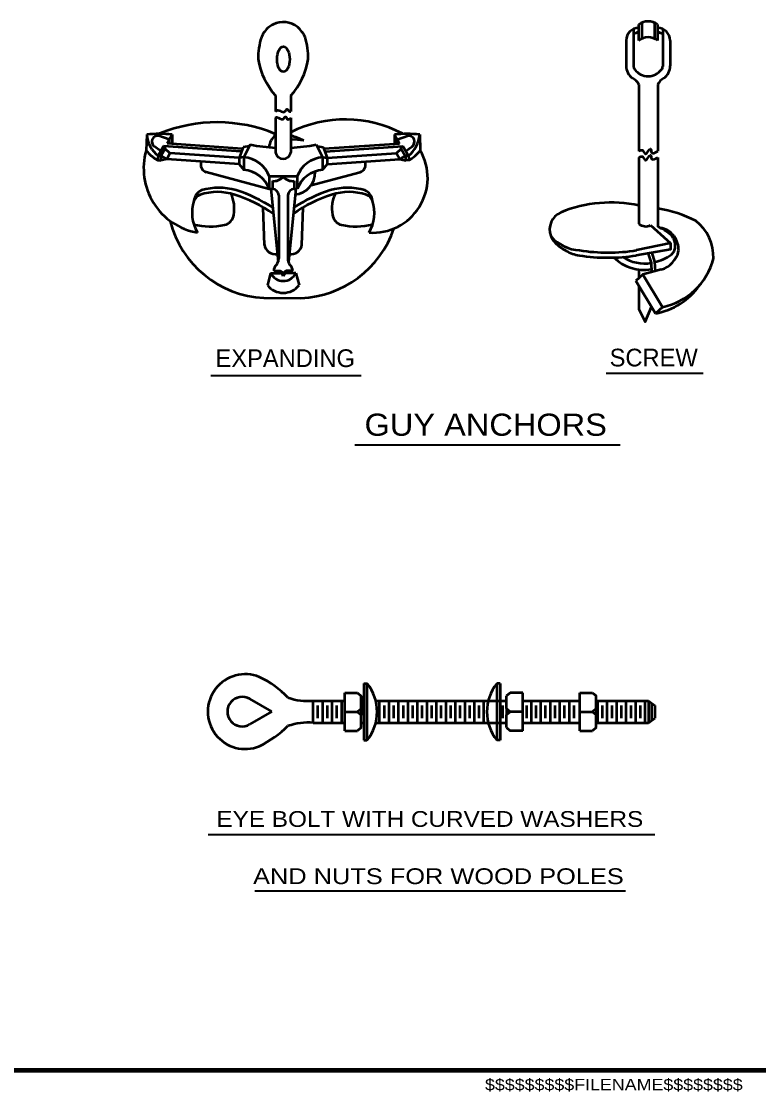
# Model space of a CAD drawing. Extents: x 14808 to 15663, y 10944 to 11488.
# Drawn here: x 15295.9 to 15435.8, y 10951.6 to 11154.7 of the extents above; entities that cross this region are included whole.
import ezdxf
from ezdxf.enums import TextEntityAlignment as Align

# ---------------------------------------------------------------- set-up
doc = ezdxf.new("R2010")
doc.units = 0
doc.header["$LTSCALE"] = 1.2
doc.layers.add('1', color=7, linetype='Continuous', lineweight=53)

msp = doc.modelspace()

# ---------------------------------------------------------------- linework, layer by layer
at = {"layer": '1'}
for p, q in [((15413.033, 11154.123), (15413.033, 11151.123)), ((15413.633, 11154.482), (15413.633, 11151.482)), ((15416.033, 11154.483), (15416.033, 11151.483)), ((15416.633, 11154.123), (15416.633, 11151.123)), ((15412.073, 11153.287), (15412.073, 11146.212)), ((15417.593, 11153.287), (15417.593, 11146.194)), ((15410.633, 11151.123), (15410.633, 11146.323)), ((15419.033, 11151.123), (15419.033, 11146.323)), ((15413.077, 11142.737), (15413.077, 11130.137)), ((15416.677, 11142.737), (15416.677, 11130.137)), ((15344.128, 11140.65), (15344.128, 11137.65)), ((15347.046, 11140.65), (15347.046, 11137.65)), ((15344.128, 11136.45), (15344.128, 11129.85)), ((15347.046, 11136.45), (15347.046, 11129.85)), ((15319.679, 11133.26), (15319.574, 11130.262)), ((15323.963, 11132.331), (15321.977, 11133.015)), ((15324.479, 11133.26), (15323.538, 11131.567)), ((15324.479, 11133.26), (15324.479, 11131.501)), ((15366.695, 11133.26), (15367.626, 11131.585)), ((15366.695, 11133.26), (15366.695, 11131.52)), ((15367.211, 11132.331), (15369.197, 11133.015)), ((15371.495, 11133.26), (15371.6, 11130.262)), ((15322.357, 11130.132), (15321.128, 11130.993)), ((15322.872, 11131.061), (15321.841, 11129.204)), ((15337.613, 11130.03), (15322.872, 11131.061)), ((15323.206, 11130.579), (15323.206, 11131.038)), ((15337.824, 11130.568), (15323.538, 11131.567)), ((15323.963, 11132.331), (15323.963, 11131.537)), ((15339.178, 11131.05), (15337.989, 11130.883)), ((15339.328, 11131.35), (15338.128, 11128.95)), ((15351.846, 11131.35), (15353.046, 11128.95)), ((15351.996, 11131.05), (15353.185, 11130.883)), ((15353.349, 11130.587), (15367.626, 11131.585)), ((15353.561, 11130.03), (15368.302, 11131.061)), ((15367.211, 11132.331), (15367.211, 11131.556)), ((15367.969, 11130.579), (15367.969, 11131.038)), ((15368.302, 11131.061), (15369.333, 11129.204)), ((15368.817, 11130.132), (15370.046, 11130.993)), ((15321.841, 11129.204), (15322.453, 11129.223)), ((15323.47, 11128.587), (15322.453, 11129.223)), ((15324.069, 11129.746), (15323.206, 11130.579)), ((15324.069, 11129.746), (15323.47, 11128.587)), ((15337.237, 11128.825), (15324.069, 11129.746)), ((15338.128, 11128.95), (15337.237, 11128.825)), ((15338.128, 11128.95), (15338.128, 11126.55)), ((15353.046, 11128.95), (15353.046, 11126.55)), ((15353.046, 11128.95), (15353.938, 11128.825)), ((15353.938, 11128.825), (15367.105, 11129.746)), ((15367.105, 11129.746), (15367.969, 11130.579)), ((15367.105, 11129.746), (15367.704, 11128.587)), ((15367.704, 11128.587), (15368.722, 11129.223)), ((15369.333, 11129.204), (15368.722, 11129.223)), ((15323.47, 11128.587), (15322.301, 11128.318)), ((15337.237, 11127.625), (15323.47, 11128.587)), ((15353.938, 11127.625), (15367.704, 11128.587)), ((15367.704, 11128.587), (15368.873, 11128.318)), ((15413.077, 11128.937), (15413.077, 11116.337)), ((15416.677, 11128.937), (15416.677, 11115.727)), ((15342.928, 11122.906), (15330.968, 11126.11)), ((15342.928, 11125.35), (15348.246, 11125.35)), ((15342.928, 11125.35), (15342.928, 11122.906)), ((15348.246, 11125.35), (15348.246, 11122.95)), ((15350.899, 11123.626), (15360.172, 11126.11)), ((15342.928, 11122.95), (15343.528, 11122.95)), ((15343.228, 11122.95), (15344.613, 11109.083)), ((15343.528, 11124.45), (15343.528, 11122.95)), ((15347.946, 11122.95), (15346.561, 11109.083)), ((15347.646, 11124.45), (15347.646, 11122.95)), ((15347.646, 11122.95), (15348.246, 11122.95)), ((15344.728, 11121.75), (15344.728, 11109.75)), ((15346.446, 11121.75), (15346.446, 11109.75)), ((15342.048, 11112.247), (15341.797, 11119.443)), ((15349.126, 11112.247), (15349.377, 11119.443)), ((15415.301, 11116.074), (15419.091, 11112.661)), ((15419.091, 11112.661), (15412.635, 11111.289)), ((15415.546, 11110.836), (15416.072, 11109.115)), ((15416.072, 11109.115), (15416.166, 11107.317)), ((15343.195, 11106.983), (15342.573, 11104.664)), ((15343.195, 11106.983), (15344.995, 11106.983)), ((15343.787, 11107.368), (15344.987, 11107.368)), ((15347.387, 11107.368), (15346.187, 11107.368)), ((15347.995, 11106.983), (15346.195, 11106.983)), ((15347.995, 11106.983), (15348.616, 11104.664)), ((15413.848, 11106.696), (15412.51, 11105.492)), ((15413.077, 11107.661), (15413.077, 11106.002)), ((15417.325, 11107.628), (15413.848, 11106.696)), ((15413.848, 11106.696), (15417.556, 11100.525)), ((15412.51, 11105.492), (15416.219, 11099.32)), ((15341.916, 11102.247), (15348.949, 11102.235)), ((15417.556, 11100.525), (15416.219, 11099.32)), ((15360.882, 11029.095), (15360.882, 11018.295)), ((15360.882, 11029.095), (15361.482, 11029.095)), ((15361.482, 11029.095), (15361.482, 11018.295)), ((15386.146, 11029.095), (15386.146, 11018.295)), ((15386.746, 11029.095), (15386.146, 11029.095)), ((15386.746, 11029.095), (15386.746, 11018.295)), ((15343.394, 11023.735), (15339.237, 11026.135)), ((15351.282, 11021.595), (15351.282, 11025.795)), ((15351.282, 11025.795), (15357.257, 11025.795)), ((15353.082, 11021.595), (15353.082, 11025.795)), ((15354.882, 11021.595), (15354.882, 11025.795)), ((15356.682, 11021.595), (15356.682, 11025.795)), ((15357.282, 11027.295), (15359.682, 11027.295)), ((15360.391, 11025.795), (15360.852, 11025.795)), ((15360.402, 11024.295), (15360.402, 11026.695)), ((15363.14, 11025.795), (15387.886, 11025.795)), ((15363.882, 11021.595), (15363.882, 11025.795)), ((15365.682, 11021.595), (15365.682, 11025.795)), ((15367.482, 11021.595), (15367.482, 11025.795)), ((15369.282, 11021.595), (15369.282, 11025.795)), ((15371.082, 11021.595), (15371.082, 11025.795)), ((15372.882, 11021.595), (15372.882, 11025.795)), ((15374.682, 11021.595), (15374.682, 11025.795)), ((15376.482, 11021.595), (15376.482, 11025.795)), ((15378.282, 11021.595), (15378.282, 11025.795)), ((15380.082, 11021.595), (15380.082, 11025.795)), ((15381.882, 11021.595), (15381.882, 11025.795)), ((15383.682, 11021.595), (15383.682, 11025.795)), ((15388.679, 11027.317), (15387.959, 11026.717)), ((15387.959, 11024.317), (15387.959, 11026.717)), ((15391.079, 11027.317), (15388.679, 11027.317)), ((15390.998, 11025.795), (15401.826, 11025.795)), ((15392.682, 11021.595), (15392.682, 11025.795)), ((15394.482, 11021.595), (15394.482, 11025.795)), ((15396.282, 11021.595), (15396.282, 11025.795)), ((15398.082, 11021.595), (15398.082, 11025.795)), ((15399.882, 11021.595), (15399.882, 11025.795)), ((15401.879, 11027.317), (15404.279, 11027.317)), ((15404.279, 11027.317), (15404.999, 11026.717)), ((15404.938, 11025.795), (15414.882, 11025.795)), ((15404.999, 11024.317), (15404.999, 11026.717)), ((15405.282, 11021.595), (15405.282, 11025.795)), ((15407.082, 11021.595), (15407.082, 11025.795)), ((15408.882, 11021.595), (15408.882, 11025.795)), ((15410.682, 11021.595), (15410.682, 11025.795)), ((15412.482, 11021.595), (15412.482, 11025.795)), ((15414.282, 11021.595), (15414.282, 11025.795)), ((15414.882, 11025.795), (15414.882, 11021.595)), ((15414.882, 11025.795), (15416.082, 11024.895)), ((15343.394, 11023.735), (15339.237, 11021.335)), ((15352.182, 11022.495), (15352.182, 11024.895)), ((15353.982, 11022.495), (15353.982, 11024.895)), ((15355.782, 11022.495), (15355.782, 11024.895)), ((15357.282, 11023.695), (15359.682, 11023.695)), ((15360.402, 11024.295), (15360.402, 11023.095)), ((15364.782, 11022.495), (15364.782, 11024.895)), ((15366.582, 11022.495), (15366.582, 11024.895)), ((15368.382, 11022.495), (15368.382, 11024.895)), ((15370.182, 11022.495), (15370.182, 11024.895)), ((15371.982, 11022.495), (15371.982, 11024.895)), ((15373.782, 11022.495), (15373.782, 11024.895)), ((15375.582, 11022.495), (15375.582, 11024.895)), ((15377.382, 11022.495), (15377.382, 11024.895)), ((15379.182, 11022.495), (15379.182, 11024.895)), ((15380.982, 11022.495), (15380.982, 11024.895)), ((15382.782, 11022.495), (15382.782, 11024.895)), ((15387.289, 11022.495), (15387.289, 11024.895)), ((15387.959, 11024.317), (15387.959, 11023.117)), ((15391.079, 11023.717), (15388.679, 11023.717)), ((15391.782, 11022.495), (15391.782, 11024.895)), ((15393.582, 11022.495), (15393.582, 11024.895)), ((15395.382, 11022.495), (15395.382, 11024.895)), ((15397.182, 11022.495), (15397.182, 11024.895)), ((15398.982, 11022.495), (15398.982, 11024.895)), ((15400.782, 11022.495), (15400.782, 11024.895)), ((15401.879, 11023.717), (15404.279, 11023.717)), ((15404.999, 11024.317), (15404.999, 11023.117)), ((15406.182, 11022.495), (15406.182, 11024.895)), ((15407.982, 11022.495), (15407.982, 11024.895)), ((15409.782, 11022.495), (15409.782, 11024.895)), ((15411.582, 11022.495), (15411.582, 11024.895)), ((15413.382, 11022.495), (15413.382, 11024.895)), ((15415.482, 11025.345), (15415.482, 11022.045)), ((15416.082, 11024.895), (15416.082, 11022.495)), ((15351.282, 11021.595), (15357.257, 11021.595)), ((15360.391, 11021.595), (15360.869, 11021.595)), ((15360.402, 11020.695), (15360.402, 11023.095)), ((15363.14, 11021.595), (15387.971, 11021.595)), ((15387.959, 11020.717), (15387.959, 11023.117)), ((15404.98, 11021.595), (15414.882, 11021.595)), ((15404.999, 11020.717), (15404.999, 11023.117)), ((15414.882, 11021.595), (15416.082, 11022.495)), ((15357.282, 11020.095), (15359.682, 11020.095)), ((15360.402, 11020.695), (15359.682, 11020.095)), ((15387.959, 11020.717), (15388.679, 11020.117)), ((15391.079, 11020.117), (15388.679, 11020.117)), ((15401.879, 11020.117), (15404.279, 11020.117)), ((15404.999, 11020.717), (15404.279, 11020.117)), ((15360.882, 11018.295), (15361.482, 11018.295)), ((15386.746, 11018.295), (15386.146, 11018.295))]:
    msp.add_line(p, q, dxfattribs=at)
at = {"layer": '1', "lineweight": 13}
msp.add_line((15413.077, 11106.08), (15413.077, 11105.845), dxfattribs=at)
at = {"layer": '1', "lineweight": 35}
for p, q in [((15331.87, 11087.501), (15360.407, 11087.501)), ((15406.847, 11087.97), (15425.297, 11087.97))]:
    msp.add_line(p, q, dxfattribs=at)
at = {"layer": '1', "lineweight": 40}
for p, q in [((15359.166, 11074.353), (15409.532, 11074.353)), ((15331.346, 11000.437), (15416.079, 11000.437)), ((15340.173, 10989.71), (15410.512, 10989.71))]:
    msp.add_line(p, q, dxfattribs=at)
at = {"layer": '1', "lineweight": 158}
msp.add_line((15656.868, 10955.64), (14865.268, 10955.64), dxfattribs=at)
at = {"layer": '1'}
for points in [[(15321.841, 11129.204), (15321.709, 11128.417), (15322.301, 11128.318)], [(15323.206, 11130.579), (15322.453, 11129.223), (15322.301, 11128.318)], [(15337.989, 11130.883), (15337.237, 11128.825), (15337.237, 11127.625), (15338.128, 11126.55)], [(15353.185, 11130.883), (15353.938, 11128.825), (15353.938, 11127.625), (15353.046, 11126.55)], [(15367.969, 11130.579), (15368.722, 11129.223), (15368.873, 11128.318)], [(15369.333, 11129.204), (15369.465, 11128.417), (15368.873, 11128.318)], [(15419.091, 11112.661), (15419.091, 11111.461), (15412.591, 11110.315)], [(15414.857, 11110.626), (15415.384, 11108.904), (15415.478, 11107.107)], [(15413.077, 11104.549), (15413.077, 11100.137), (15414.277, 11097.737), (15415.478, 11100.553)], [(15357.282, 11020.095), (15357.282, 11023.695), (15357.282, 11027.295)], [(15359.682, 11027.295), (15360.402, 11026.695), (15360.402, 11024.295), (15359.682, 11023.695), (15360.402, 11023.095)], [(15391.079, 11020.117), (15391.079, 11023.717), (15391.079, 11027.317)], [(15401.879, 11020.117), (15401.879, 11023.717), (15401.879, 11027.317)], [(15387.959, 11024.317), (15388.679, 11023.717), (15387.959, 11023.117)], [(15404.999, 11024.317), (15404.279, 11023.717), (15404.999, 11023.117)], [(15391.04, 11021.595), (15401.826, 11021.595), (15401.868, 11021.595)]]:
    msp.add_lwpolyline(points, dxfattribs=at)
for centre, radius, start, end in [((15346.686, 11149.383), 5.756, 131.96494, 155.64508), ((15345.449, 11150.126), 4.397, 114.18463, 126.44768), ((15345.621, 11150.226), 4.38, 51.67793, 116.77606), ((15344.488, 11149.383), 5.756, 24.35492, 48.03506), ((15413.141, 11151.016), 2.51, 92.45547, 177.54453), ((15414.834, 11151.794), 2.944, 52.29201, 127.70799), ((15416.526, 11151.016), 2.51, 2.45547, 87.54453), ((15354.952, 11147.635), 14.125, 163.03649, 180.34718), ((15336.222, 11147.635), 14.125, 359.65283, 16.96351), ((15412.993, 11151.288), 1.336, 88.28293, 133.52461), ((15414.834, 11148.794), 2.944, 52.29201, 127.70799), ((15416.673, 11151.288), 1.336, 46.47539, 91.71707), ((15354.66, 11149.926), 14.034, 189.74744, 221.3725), ((15336.514, 11149.926), 14.034, 318.6275, 350.25256), ((15413.586, 11146.346), 2.953, 180.43177, 234.62969), ((15412.968, 11146.198), 0.895, 179.14798, 220.24311), ((15414.833, 11147.535), 3.187, 216.91814, 322.98043), ((15416.695, 11146.194), 0.895, 319.75689, 0.85202), ((15416.08, 11146.346), 2.953, 305.37031, 359.56823), ((15410.833, 11141.694), 2.474, 24.94304, 65.05696), ((15418.847, 11141.841), 2.348, 116.76572, 157.56298), ((15333.046, 11106.837), 28.749, 67.32753, 112.30219), ((15357.361, 11112.815), 23.312, 62.24214, 116.49544), ((15322.079, 11110.396), 22.989, 84.00757, 95.99243), ((15325.565, 11133.793), 5.91, 185.18056, 230.94579), ((15321.763, 11131.916), 1.12, 78.96142, 235.46809), ((15346.185, 11130.561), 3.307, 128.46984, 175.06692), ((15342.907, 11118.266), 15.343, 64.65247, 74.23543), ((15369.095, 11110.396), 22.989, 84.00757, 95.99243), ((15369.375, 11131.901), 1.129, 306.45493, 99.11556), ((15365.609, 11133.793), 5.91, 309.05421, 354.81944), ((15346.912, 11172.521), 41.864, 259.56289, 266.18708), ((15344.262, 11172.521), 41.864, 273.81292, 280.43711), ((15347.546, 11120.615), 11.678, 80.48984, 92.29918), ((15331.494, 11126.847), 12.4, 164.01359, 259.79898), ((15325.267, 11134.692), 7.214, 217.89069, 240.44911), ((15337.732, 11123.423), 5.541, 20.35078, 85.90942), ((15345.587, 11130.144), 1.489, 191.39485, 348.60515), ((15353.442, 11123.423), 5.541, 94.09058, 159.64922), ((15362.574, 11125.045), 10.425, 266.16365, 30.02378), ((15365.907, 11134.692), 7.214, 299.55089, 322.10931), ((15331.461, 11127.573), 1.544, 158.99371, 251.37679), ((15359.678, 11127.573), 1.544, 288.62321, 21.00629), ((15337.732, 11121.023), 5.541, 20.35078, 85.90942), ((15343.792, 11126.86), 2.424, 263.73433, 317.75599), ((15347.382, 11126.86), 2.424, 222.24401, 276.26567), ((15347.508, 11126.015), 4.127, 273.98395, 2.60406), ((15353.442, 11121.023), 5.541, 94.09058, 159.64922), ((15333.375, 11111.396), 11.775, 73.72458, 106.27542), ((15343.369, 11121.591), 1.368, 6.66371, 83.33629), ((15347.805, 11121.591), 1.368, 96.66371, 173.33629), ((15357.799, 11111.396), 11.775, 73.72458, 106.27542), ((15331.152, 11120.403), 2.536, 115.12547, 173.42944), ((15330.931, 11119.529), 2.577, 116.11742, 153.15373), ((15333.097, 11111.578), 10.782, 72.17801, 107.82199), ((15330.044, 11119.265), 6.26, 348.82631, 26.25382), ((15327.653, 11094.905), 28.321, 55.49077, 72.01683), ((15327.653, 11094.905), 29.221, 56.96697, 72.01675), ((15363.521, 11094.905), 28.321, 107.98317, 124.50923), ((15363.521, 11094.905), 29.221, 107.98325, 123.03303), ((15358.077, 11111.578), 10.782, 72.17801, 107.82199), ((15361.066, 11119.265), 6.26, 153.74618, 191.17369), ((15360.022, 11120.403), 2.536, 6.57056, 64.87453), ((15360.243, 11119.529), 2.577, 26.84627, 63.88258), ((15335.762, 11118.416), 7.484, 162.29086, 210.27517), ((15355.412, 11118.416), 7.484, 329.72483, 17.70914), ((15407.746, 11095.675), 24.689, 77.48956, 112.53539), ((15412.56, 11094.464), 25.119, 63.12438, 80.5666), ((15342.942, 11121.654), 19.435, 194.44102, 266.97322), ((15333.994, 11118.273), 2.202, 282.14771, 354.26068), ((15357.116, 11118.273), 2.202, 185.73932, 257.85229), ((15399.616, 11115.272), 3.473, 112.56326, 201.22601), ((15418.78, 11110.143), 8.446, 357.06801, 53.01462), ((15331.718, 11128.771), 12.945, 256.06592, 282.21618), ((15348.168, 11121.654), 19.435, 272.30306, 341.28411), ((15359.391, 11128.771), 12.945, 257.78382, 283.93408), ((15414.375, 11117.776), 1.937, 227.92906, 298.55891), ((15414.216, 11108.837), 7.316, 47.97836, 70.34854), ((15416.959, 11112.409), 3.121, 60.03867, 86.11071), ((15416.177, 11111.29), 4.483, 37.20204, 58.52155), ((15457.843, 11142.762), 67.855, 205.06602, 205.618), ((15402.298, 11119.171), 7.896, 221.76894, 266.63849), ((15399.739, 11115.142), 3.523, 205.89722, 222.96556), ((15403.116, 11118.81), 8.503, 225.54603, 243.17205), ((15416.764, 11112.094), 3.204, 345.49101, 42.81927), ((15416.137, 11111.329), 4.492, 358.21611, 36.4931), ((15344.088, 11112.623), 2.074, 186.64556, 280.42286), ((15347.086, 11112.623), 2.074, 259.57714, 353.35444), ((15402.861, 11117.209), 6.977, 239.10628, 261.18034), ((15407.235, 11146.123), 35.251, 261.18821, 278.81179), ((15415.822, 11112.332), 4.938, 287.7219, 346.62294), ((15417.654, 11112.414), 2.48, 310.05064, 333.08561), ((15342.185, 11109.843), 2.545, 329.93461, 357.90459), ((15348.989, 11109.843), 2.545, 182.09541, 210.06539), ((15407.191, 11145.15), 35.251, 261.18821, 278.81179), ((15414.131, 11116.056), 8.461, 226.52134, 278.94966), ((15414.131, 11116.056), 7.261, 235.85618, 279.93742), ((15414.111, 11117.403), 8.593, 282.93456, 306.7285), ((15414.983, 11112.9), 12.64, 281.74498, 345.38421), ((15345.595, 11108.153), 2.67, 205.98923, 334.01077), ((15345.289, 11107.367), 1.502, 126.91323, 179.95667), ((15344.851, 11106.632), 0.748, 10.44919, 79.5508), ((15344.859, 11106.247), 0.748, 10.44919, 79.5508), ((15346.323, 11106.632), 0.748, 100.4492, 169.55081), ((15346.33, 11106.247), 0.748, 100.4492, 169.55081), ((15345.885, 11107.367), 1.502, 0.04333, 53.08677), ((15345.595, 11107.12), 3.893, 219.10281, 320.89719), ((15414.089, 11111.843), 12.703, 279.6497, 325.48694), ((15338.371, 11023.742), 7.095, 67.37581, 292.62419), ((15333.175, 11013.68), 18.405, 43.69833, 64.49446), ((15354.848, 11023.695), 8.554, 320.85375, 39.14625), ((15392.78, 11023.695), 8.554, 140.85375, 219.14625), ((15337.794, 11023.735), 2.8, 58.9871, 301.0129), ((15350.308, 11037.505), 11.75, 250.99574, 274.75423), ((15350.308, 11009.901), 11.75, 85.24577, 109.00426), ((15331.185, 11036.873), 22.037, 296.74116, 313.96028)]:
    msp.add_arc(centre, radius, start, end, dxfattribs=at)
msp.add_ellipse((15345.628, 11147.55), major_axis=(0, -2.4), ratio=0.5, dxfattribs=at)
for points in [[(15344.128, 11137.65), (15344.586, 11137.895), (15345.065, 11137.745), (15345.903, 11137.626), (15346.293, 11138.105), (15346.772, 11137.656), (15347.046, 11137.65)], [(15344.128, 11136.45), (15344.376, 11136.533), (15345.544, 11136.203), (15346.053, 11136.652), (15346.323, 11136.203), (15347.046, 11136.45)], [(15413.077, 11130.137), (15413.736, 11130.274), (15414.321, 11129.6), (15415.288, 11130.537), (15415.493, 11129.864), (15416.677, 11130.137)], [(15413.077, 11128.937), (15413.736, 11129.074), (15414.321, 11128.4), (15415.288, 11129.337), (15415.493, 11128.664), (15416.677, 11128.937)]]:
    msp.add_spline(points, degree=3, dxfattribs=at)

# ---------------------------------------------------------------- texts
for s, p in [('EXPANDING', (15345.963, 11089.137)), ('SCREW', (15415.889, 11089.254))]:
    msp.add_text(s, height=3.36, dxfattribs=at).set_placement(p, align=Align.CENTER)
for s, height, width, p in [('GUY ANCHORS', 4.2, 1.1, (15384.01, 11076.092)), ('EYE BOLT WITH CURVED WASHERS', 3, 1.15, (15373.406, 11001.861)), ('AND NUTS FOR WOOD POLES', 3, 1.2, (15375.035, 10990.998))]:
    msp.add_text(s, height=height, dxfattribs=dict(at, width=width)).set_placement(p, align=Align.CENTER)
at = {"layer": '1', "width": 1.15}
msp.add_text('$$$$$$$$$FILENAME$$$$$$$$', height=2.2, dxfattribs=at).set_placement((15383.868, 10951.84))

doc.saveas('drawing.dxf')
